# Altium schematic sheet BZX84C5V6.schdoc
size 127 x 101 mm
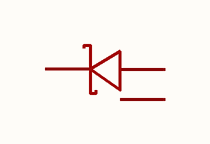
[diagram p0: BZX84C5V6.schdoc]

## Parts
D?  bzx84c5v6  [SOT-23_L2.9-W1.3-P1.90-LS2.4-BR]  (value not drawn)

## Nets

Not connected (* = marked no-connect by the designer): D? 1 2 3

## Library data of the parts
D? = bzx84c5v6: 二极管配置:1个独立式;稳压值(标称值):5.6V;稳压值(范围):5.2V~6V;耗散功率(Pd):300mW;; Manufacturer: CJ(江苏长电/长晶); AddInBom: yes; ModelId: c62791f0466c4ae2a892c056b845b0ca; ModelName: SOT-23-3P_L2.9-W1.3-H1.0-LS2.4-P0.95; ModelTransform: 98.64468,114.173,0,180,0,0,0.001,-0.002,0; Diode Configuration: 1个独立式; Zener Voltage(Nom): 5.6V; Reverse Leakage Current (Ir): 1uA; Pd - Power Dissipation: 300mW; Impedance(Zzt): 40Ω; Impedance(Zzk): 400Ω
